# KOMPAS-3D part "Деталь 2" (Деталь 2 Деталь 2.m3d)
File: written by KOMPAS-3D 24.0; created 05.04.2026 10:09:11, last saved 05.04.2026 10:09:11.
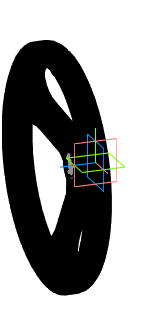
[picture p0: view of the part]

Document properties: Автор: R2D2; Полное имя файла: E:\Работа\Зайцев\Аксессуары для пневмоприводов\Ручной дублер DN.ru\MON3-700-T38-ISO Ручной дублер DN.ru\исходные материалы\Деталь 2 Деталь 2.m3d

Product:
- Body: Твердое тело1  | qty 1
- Part/product: Деталь 2
    additional columns: Типовые

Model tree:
1. Твердое тело1  (labels: Твердое тело1)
